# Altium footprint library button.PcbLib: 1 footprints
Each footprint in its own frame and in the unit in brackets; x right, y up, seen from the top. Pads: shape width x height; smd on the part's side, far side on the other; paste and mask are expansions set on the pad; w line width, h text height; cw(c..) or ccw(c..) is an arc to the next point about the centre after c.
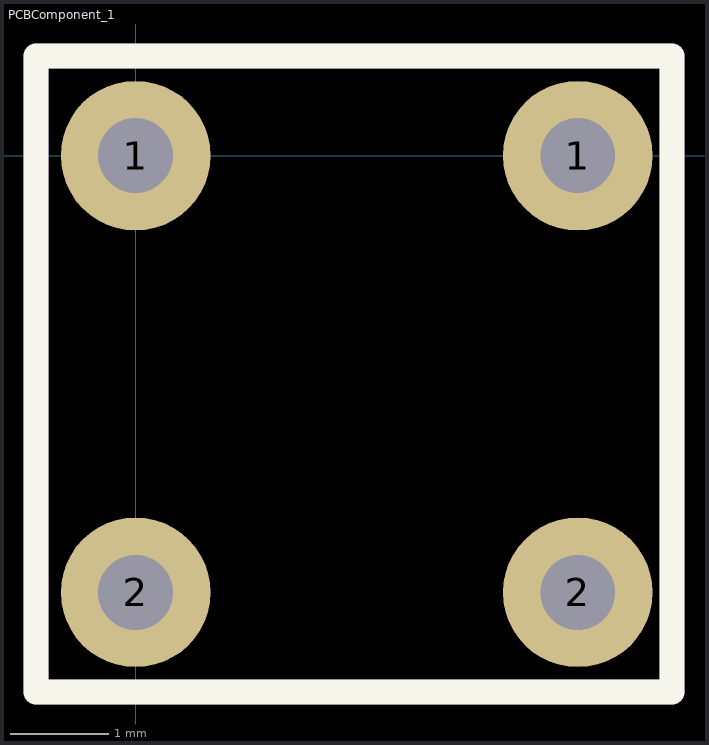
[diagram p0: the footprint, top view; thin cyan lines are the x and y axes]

## PCBComponent_1 [mil]
pads (4):
  round 60 hole 30: 1(0,0) 1(177.17,0) 2(0,-175) 2(177.17,-175)
Top Overlay:
  lines w10: -40,-215 -40,40 215,40 215,-215 -40,-215
Mechanical 1:
  lines w10: -40,-215 215,-215 215,40 -40,40 -40,-215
